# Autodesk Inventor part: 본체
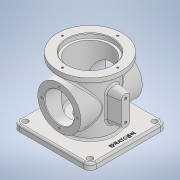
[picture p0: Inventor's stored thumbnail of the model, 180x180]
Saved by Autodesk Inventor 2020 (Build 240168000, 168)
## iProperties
Created: 2017-08
Part Number: 본체
Material: 알루미늄 6061
Document SubType Name: Modeling
Designer: mduedu
Density: 2.71 g/cm^3
Mass: 951.115 g
Surface Area: 966.539 cm^2
Volume: 350.965 cm^3
Appearance: 기본값
Author: mduedu
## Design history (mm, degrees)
sketch "스케치1"
  geometry: L1 (-62.5, -62.5)-(62.5, -62.5); L2 (62.5, -62.5)-(62.5, 62.5); L3 (62.5, 62.5)-(-62.5, 62.5); L4 (-62.5, 62.5)-(-62.5, -62.5); L5 (-62.5, -62.5)-(62.5, 62.5); L6 (62.5, -62.5)-(-62.5, 62.5); 1 further point
  constraints: 12 end point, 2 midpoint, 2 parallel, 1 horizontal, 1 perpendicular
  dimensions: "d232" = 125 distance of L3.end L2.end; "d233" = 125 distance of L2.end L1.end
extrude "돌출1" new body sketch "스케치1" distance "d5" = 10; taper "d6" = 0 deg
sketch "스케치2"
  geometry: C1 r 38 at (0, 0); 1 further point
  constraints: 1 centre point, 1 coincident
  dimensions: "d111" = 76 diameter of C1
extrude "돌출2" join sketch "스케치2" distance "d12" = 88; taper "d13" = 0 deg
sketch "스케치3"
  geometry: C1 r 52.5 at (0, 0); 1 further point
  constraints: 1 centre point, 1 coincident
  dimensions: "d114" = 105 diameter of C1
extrude "돌출3" join sketch "스케치3" distance "d19" = 10; taper "d20" = 0 deg
sketch "스케치4"
  geometry: C1 r 33 at (0, 0); 1 further point
  constraints: 1 centre point, 1 coincident
  dimensions: "d115" = 66 diameter of C1
extrude "돌출4" cut sketch "스케치4" distance "d26" = 86; taper "d27" = 0 deg
sketch "스케치5"
  geometry: C1 r 37 at (0, 0); 1 further point
  constraints: 1 centre point, 1 coincident
  dimensions: "d116" = 74 diameter of C1
extrude "돌출5" cut sketch "스케치5" distance "d29" = 7; taper "d30" = 0 deg
node "작업 평면1"
sketch "스케치18"
  geometry: L1 (-62.5, 0)-(62.5, 0) reference; C1 r 35 at (0, 54); 1 further point
  constraints: 1 centre point, 1 vertical alignment
  dimensions: "d118" = 70 diameter of C1; "d234" = 54 distance from line of C1.centre L1
extrude "돌출9" join sketch "스케치18" stored distance "d120" = 10; taper "d121" = 0 deg
hole "구멍8" diameter "d124" = 48; stored, may be unused: countersink angle "d128" = 90 deg, drill point angle "d130" = 118 deg; dims "d122" = 10, "d123" = 10, "d125" = 6, "d126" = 4, "d127" = 2, "d129" = 8
sketch "스케치9"
  geometry: C1 r 33 at (0, 0); 1 further point
  constraints: 1 centre point, 1 coincident
  dimensions: "d131" = 66 diameter of C1
extrude "돌출8" cut sketch "스케치9" distance "d43" = 16; taper "d44" = 0 deg
node "작업 평면2"
fillet "모깎기9" dims "d137" = 3
fillet "모깎기10" dims "d138" = 3
chamfer "모따기2" distance "d139" = 1; stored, may be unused: second distance "d140" = 2, angle "d141" = 45 deg
fillet "모깎기11" dims "d142" = 3
fillet "모깎기12" dims "d143" = 3
fillet "모깎기13" dims "d144" = 3
node "작업 평면3"
sketch "스케치20"
  geometry: L1 (108, -52.5)-(108, 52.5) reference; L2 (37, 7)-(71, 7); L3 (37, -7)-(71, -7); L4 (0, -33)-(0, 33) reference; A1 r 7 centre (37, 0) between (37, 7) and (37, -7); A2 r 7 centre (71, 0) between (71, 7) and (71, -7); 1 further point
  constraints: 4 end point, 4 point on circle, 3 tangent, 2 centre point, 2 horizontal alignment, 1 parallel, 1 perpendicular
  dimensions: "d203" = 14 diameter of A1; "d206" = 30 distance edge to line of A2 L1; "d207" = 48 dimension on A2 A1 (derived); "d236" = 30 distance edge to line of A1 L4
extrude "돌출10" join sketch "스케치20" stored distance "d152" = 10; taper "d153" = 10 deg
sketch "스케치21"
  geometry: C1 r 7 at (0, 71) reference; C2 r 7 at (0, 37) reference; 3 further points
  constraints: 2 coincident
hole "구멍12" sketch "스케치21" at (0, 71), (0, 37) diameter "d219" = 4.134; stored, may be unused: countersink angle "d223" = 90 deg, drill point angle "d225" = 118 deg; dims "d220" = 6, "d221" = 4, "d222" = 2, "d224" = 8
fillet "모깎기18" dims "d229" = 3
sketch "스케치23"
  geometry: C1 r 20 at (0, 0); 1 further point
  constraints: 1 centre point, 1 coincident
  dimensions: "d168" = 40 diameter of C1
extrude "돌출12" cut sketch "스케치23" extent not by distance; stored distance "d169" = 148.25; taper "d170" = 0 deg
sketch "스케치28"
  geometry: L1 (62.5, -62.5)-(62.5, 62.5) reference; 2 further points
  constraints: 1 horizontal alignment, 1 other
  dimensions: "d238" = 10 distance from line of point (52.5, 0) L1
feature "엠보싱4" sketch "스케치28" dims "d239" = 0.5, "d240" = 0
sketch "스케치25" dims "d178" = 58
  geometry: C1 r 35 at (0, 0) reference; 3 further points
  constraints: 2 vertical alignment, 1 coincident, 2 other
hole "구멍10" sketch "스케치25" at (0, 29) diameter "d179" = 3.242; stored, may be unused: countersink angle "d183" = 90 deg, drill point angle "d185" = 118 deg; dims "d180" = 4, "d181" = 4, "d182" = 2, "d184" = 6
sketch "스케치26" dims "d189" = 90
  geometry: 3 further points
  constraints: 2 vertical alignment, 1 coincident, 2 other
hole "구멍11" sketch "스케치26" at (0, 45) diameter "d190" = 3.242; stored, may be unused: countersink angle "d194" = 90 deg, drill point angle "d196" = 118 deg; dims "d191" = 4, "d192" = 4, "d193" = 2, "d195" = 6
chamfer "모따기4" distance "d200" = 1; stored, may be unused: second distance "d201" = 2, angle "d202" = 45 deg
fillet "모깎기19" dims "d241" = 10
sketch "스케치29"
  geometry: A1 r 10 centre (-52.5, 52.5) between (-52.5, 62.5) and (-62.5, 52.5) reference; A2 r 10 centre (52.5, 52.5) between (62.5, 52.5) and (52.5, 62.5) reference; A3 r 10 centre (52.5, -52.5) between (52.5, -62.5) and (62.5, -52.5) reference; A4 r 10 centre (-52.5, -52.5) between (-62.5, -52.5) and (-52.5, -62.5) reference; 5 further points
  constraints: 4 coincident
hole "구멍13" sketch "스케치29" at (-52.5, 52.5), (52.5, 52.5), (52.5, -52.5), (-52.5, -52.5) diameter "d242" = 9; stored, may be unused: countersink angle "d246" = 90 deg, drill point angle "d248" = 118 deg; dims "d243" = 6, "d244" = 4, "d245" = 2, "d247" = 8
fillet "모깎기20" dims "d249" = 3
node "솔리드1"
mirror "대칭2"
pattern_circular "원형 패턴1" dims angle "d187" = 360 deg
mirror "대칭3"
pattern_circular "원형 패턴2" dims angle "d198" = 360 deg
other parameters: "d147" = 58
